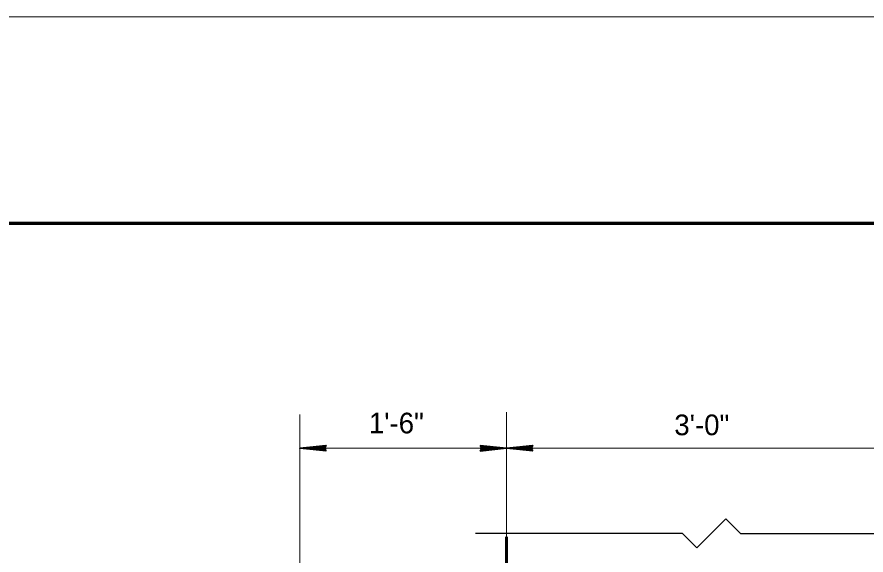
# Model space of a CAD drawing. Extents: x 4.49 to 7.69, y 0.28 to 2.27.
# Drawn here: x 5.7423 to 6.0846, y 2.0525 to 2.2695 of the extents above; entities that cross this region are included whole.
import ezdxf

# ---------------------------------------------------------------- set-up
doc = ezdxf.new("R2010")
doc.units = 0
doc.header["$LTSCALE"] = 0.0033
doc.layers.add('1', color=7, linetype='Continuous', lineweight=35)

msp = doc.modelspace()

# ---------------------------------------------------------------- linework, layer by layer
at = {"layer": '1', "lineweight": 13}
for p, q in [((4.492417, 2.2695), (7.688833, 2.2695)), ((5.856333, 1.960667), (5.856333, 2.10925)), ((5.939667, 2.059833), (5.939667, 2.110083)), ((5.856917, 2.095583), (6.187167, 2.095583))]:
    msp.add_line(p, q, dxfattribs=at)
at = {"layer": '1'}
for p, q in [((5.866917, 2.095583), (5.856333, 2.095583)), ((5.866667, 2.09475), (5.858833, 2.09575)), ((5.866667, 2.09475), (5.858833, 2.095583)), ((5.866667, 2.094583), (5.858833, 2.0955)), ((5.866667, 2.094583), (5.858833, 2.0955)), ((5.866667, 2.094667), (5.858833, 2.0955)), ((5.866667, 2.096667), (5.859333, 2.095833)), ((5.866667, 2.0965), (5.859333, 2.09575)), ((5.866667, 2.096417), (5.859333, 2.095583)), ((5.86675, 2.09625), (5.859417, 2.0955)), ((5.929083, 2.095583), (5.939667, 2.095583)), ((5.92925, 2.094917), (5.936583, 2.095667)), ((5.929333, 2.096583), (5.937167, 2.095667)), ((5.929333, 2.096583), (5.937167, 2.095667)), ((5.929333, 2.0965), (5.937167, 2.095667)), ((5.929333, 2.096417), (5.937167, 2.095583)), ((5.929333, 2.096417), (5.937167, 2.095417)), ((5.929333, 2.09475), (5.936667, 2.095583)), ((5.929333, 2.094667), (5.936667, 2.095417)), ((5.929333, 2.0945), (5.936667, 2.095333)), ((5.95025, 2.095583), (5.939667, 2.095583)), ((5.95, 2.09475), (5.942167, 2.09575)), ((5.95, 2.09475), (5.942167, 2.095583)), ((5.95, 2.094583), (5.942167, 2.0955)), ((5.95, 2.094583), (5.942167, 2.0955)), ((5.95, 2.094667), (5.942167, 2.0955)), ((5.95, 2.096667), (5.942667, 2.095833)), ((5.95, 2.0965), (5.942667, 2.09575)), ((5.95, 2.096417), (5.942667, 2.095583)), ((5.950083, 2.09625), (5.94275, 2.0955))]:
    msp.add_line(p, q, dxfattribs=at)
at = {"layer": '1', "lineweight": 70}
msp.add_lwpolyline([(7.605833, 0.366083), (7.605833, 2.186167), (4.659167, 2.186167), (4.659167, 0.366083)], dxfattribs=at)
at = {"layer": '1'}
for points in [[(5.866917, 2.0945), (5.856333, 2.095583), (5.866917, 2.09675), (5.866333, 2.095583)], [(5.866167, 2.0955), (5.8615, 2.095417), (5.8615, 2.0955), (5.862417, 2.0955), (5.866167, 2.095417), (5.863167, 2.095333), (5.866333, 2.09525), (5.864083, 2.095167), (5.866333, 2.095083), (5.862833, 2.095333), (5.858167, 2.0955), (5.859083, 2.09575), (5.857833, 2.09575), (5.866167, 2.09575), (5.86375, 2.095917), (5.866333, 2.095917), (5.861, 2.0955), (5.866333, 2.096167)], [(5.929083, 2.096667), (5.939667, 2.095583), (5.929083, 2.094417), (5.929667, 2.095583)], [(5.929833, 2.095667), (5.9345, 2.09575), (5.9345, 2.095667), (5.933583, 2.095667), (5.929833, 2.09575), (5.932833, 2.095833), (5.929667, 2.095917), (5.931917, 2.096), (5.929667, 2.096083), (5.933167, 2.095833), (5.937833, 2.095667), (5.936917, 2.095417), (5.938167, 2.095417), (5.929833, 2.095417), (5.93225, 2.09525), (5.929667, 2.09525), (5.935, 2.095667), (5.929667, 2.095)], [(5.95025, 2.0945), (5.939667, 2.095583), (5.95025, 2.09675), (5.949667, 2.095583)], [(5.9495, 2.0955), (5.944833, 2.095417), (5.944833, 2.0955), (5.94575, 2.0955), (5.9495, 2.095417), (5.9465, 2.095333), (5.949667, 2.09525), (5.947417, 2.095167), (5.949667, 2.095083), (5.946167, 2.095333), (5.9415, 2.0955), (5.942417, 2.09575), (5.941167, 2.09575), (5.9495, 2.09575), (5.947083, 2.095917), (5.949667, 2.095917), (5.944333, 2.0955), (5.949667, 2.096167)]]:
    msp.add_lwpolyline(points, close=True, dxfattribs=at)
for points in [[(5.866167, 2.0955), (5.866583, 2.09475), (5.866333, 2.095), (5.866167, 2.095333), (5.865917, 2.09525), (5.866083, 2.094917), (5.86625, 2.095667), (5.866417, 2.096167), (5.866667, 2.096583)], [(5.929833, 2.095667), (5.929417, 2.096417), (5.929667, 2.096167), (5.929833, 2.095833), (5.930083, 2.095917), (5.929917, 2.09625), (5.92975, 2.0955), (5.929583, 2.095), (5.929333, 2.094583)], [(5.9495, 2.0955), (5.949917, 2.09475), (5.949667, 2.095), (5.9495, 2.095333), (5.94925, 2.09525), (5.949417, 2.094917), (5.949583, 2.095667), (5.94975, 2.096167), (5.95, 2.096583)]]:
    msp.add_lwpolyline(points, dxfattribs=at)
at = {"layer": '1', "lineweight": 25}
msp.add_lwpolyline([(5.927167, 2.061333), (6.0105, 2.061333), (6.016417, 2.055417), (6.028167, 2.067167), (6.034083, 2.06125), (6.117417, 2.06125)], dxfattribs=at)
at = {"layer": '1', "lineweight": 60}
msp.add_lwpolyline([(5.856333, 1.955667), (5.939667, 1.955667), (5.939667, 2.059833)], dxfattribs=at)

# ---------------------------------------------------------------- texts
at = {"layer": '1'}
for s, p in [('1\'-6"', (5.884167, 2.101583)), ('3\'-0"', (6.007333, 2.100833))]:
    msp.add_text(s, height=0.008333, dxfattribs=at).set_placement(p)

doc.saveas('drawing.dxf')
